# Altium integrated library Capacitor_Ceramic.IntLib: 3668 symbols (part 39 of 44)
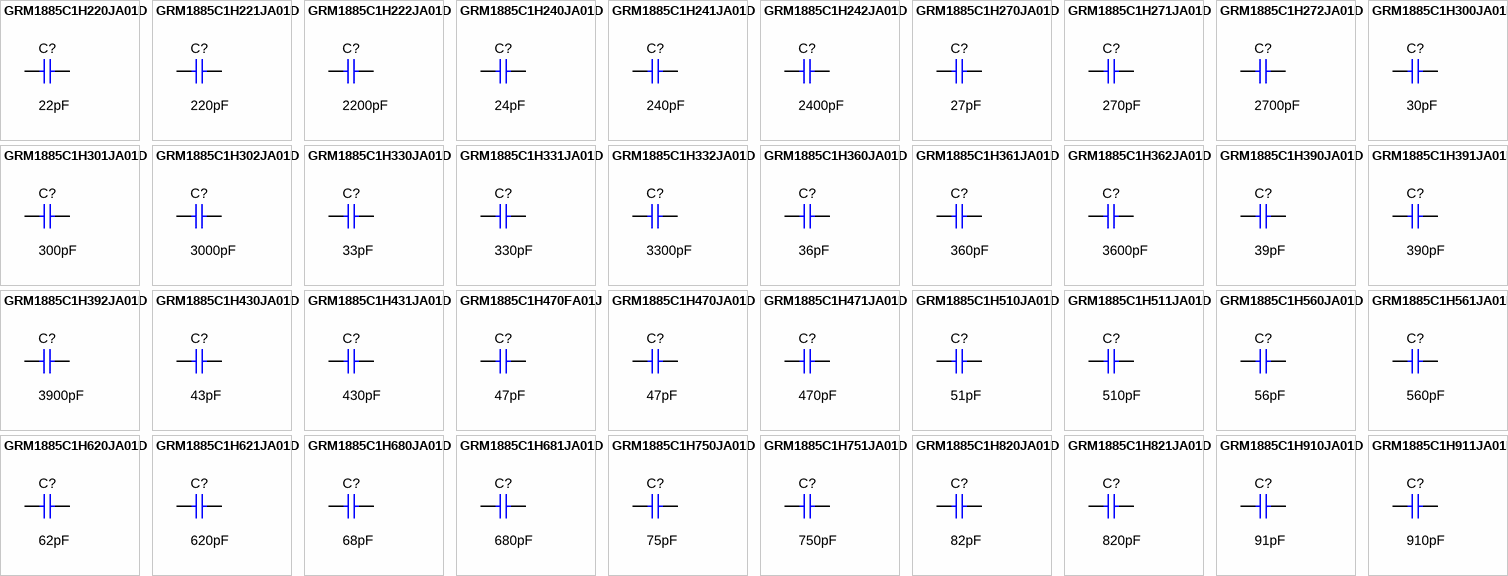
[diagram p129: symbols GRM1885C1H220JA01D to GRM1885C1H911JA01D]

## GRM1885C1H751JA01D
designator C?  ValueDisplayed: 750pF  (hidden comment: GRM1885C1H751JA01D)
CAP, CERM, 750 pF, 50 V,+/- 5%, C0G/NP0, 0603; Manufacturer: MuRata; Polarized: N; CompType: Capacitor; Value: 750pF; U/M: EA; Cap_F: 0.00000000075; Tolerance_%: 5; VDC_V: 50; Value2: 50V; TaMin_C: -55; TaMax_C: 125; Cap_Case: 0603; SizeArea_mm2: 1.28; SizeAreaWB_mm2: 4.68; SizeX_mm: 1.6; SizeY_mm: 0.8; SizeZ_mm: 1; AEC Category: Q200; Green_Lifecycle: Active; Green_REACh: Passed
signal-integrity model Cap
simulation model Cap
footprint 0603
footprint 0603M
footprint 0603L
footprint 0603_HV
footprint 0603S
pins: 1, 2

## GRM1885C1H820JA01D
designator C?  ValueDisplayed: 82pF  (hidden comment: GRM1885C1H820JA01D)
CAP, CERM, 82 pF, 50 V,+/- 5%, C0G/NP0, 0603; Manufacturer: MuRata; Polarized: N; CompType: Capacitor; Value: 82pF; U/M: EA; Cap_F: 0.000000000082; Tolerance_%: 5; VDC_V: 50; Value2: 50V; TaMin_C: -55; TaMax_C: 125; Cap_Case: 0603; SizeArea_mm2: 1.28; SizeAreaWB_mm2: 4.68; SizeX_mm: 1.6; SizeY_mm: 0.8; SizeZ_mm: 1; AEC Category: Q200; Green_Lifecycle: Active; Green_REACh: Passed
signal-integrity model Cap
simulation model Cap
footprint 0603
footprint 0603M
footprint 0603L
footprint 0603_HV
footprint 0603S
pins: 1, 2

## GRM1885C1H821JA01D
designator C?  ValueDisplayed: 820pF  (hidden comment: GRM1885C1H821JA01D)
CAP, CERM, 820 pF, 50 V,+/- 5%, C0G/NP0, 0603; Manufacturer: MuRata; Polarized: N; CompType: Capacitor; Value: 820pF; U/M: EA; Cap_F: 0.00000000082; Tolerance_%: 5; VDC_V: 50; Value2: 50V; TaMin_C: -55; TaMax_C: 125; Cap_Case: 0603; SizeArea_mm2: 1.28; SizeAreaWB_mm2: 4.68; SizeX_mm: 1.6; SizeY_mm: 0.8; SizeZ_mm: 1; AEC Category: Q200; Green_Lifecycle: Active; Green_REACh: Passed
signal-integrity model Cap
simulation model Cap
footprint 0603
footprint 0603M
footprint 0603L
footprint 0603_HV
footprint 0603S
pins: 1, 2

## GRM1885C1H910JA01D
designator C?  ValueDisplayed: 91pF  (hidden comment: GRM1885C1H910JA01D)
CAP, CERM, 91 pF, 50 V,+/- 5%, C0G/NP0, 0603; Manufacturer: MuRata; Polarized: N; CompType: Capacitor; Value: 91pF; U/M: EA; Cap_F: 0.000000000091; Tolerance_%: 5; VDC_V: 50; Value2: 50V; TaMin_C: -55; TaMax_C: 125; Cap_Case: 0603; SizeArea_mm2: 1.28; SizeAreaWB_mm2: 4.68; SizeX_mm: 1.6; SizeY_mm: 0.8; SizeZ_mm: 1; AEC Category: Q200
signal-integrity model Cap
simulation model Cap
footprint 0603
footprint 0603M
footprint 0603L
footprint 0603_HV
footprint 0603S
pins: 1, 2

## GRM1885C1H911JA01D
designator C?  ValueDisplayed: 910pF  (hidden comment: GRM1885C1H911JA01D)
CAP, CERM, 910 pF, 50 V,+/- 5%, C0G/NP0, 0603; Manufacturer: MuRata; Polarized: N; CompType: Capacitor; Value: 910pF; U/M: EA; Cap_F: 0.00000000091; Tolerance_%: 5; VDC_V: 50; Value2: 50V; TaMin_C: -55; TaMax_C: 125; Cap_Case: 0603; SizeArea_mm2: 1.28; SizeAreaWB_mm2: 4.68; SizeX_mm: 1.6; SizeY_mm: 0.8; SizeZ_mm: 1; AEC Category: Q200
signal-integrity model Cap
simulation model Cap
footprint 0603
footprint 0603M
footprint 0603L
footprint 0603_HV
footprint 0603S
pins: 1, 2

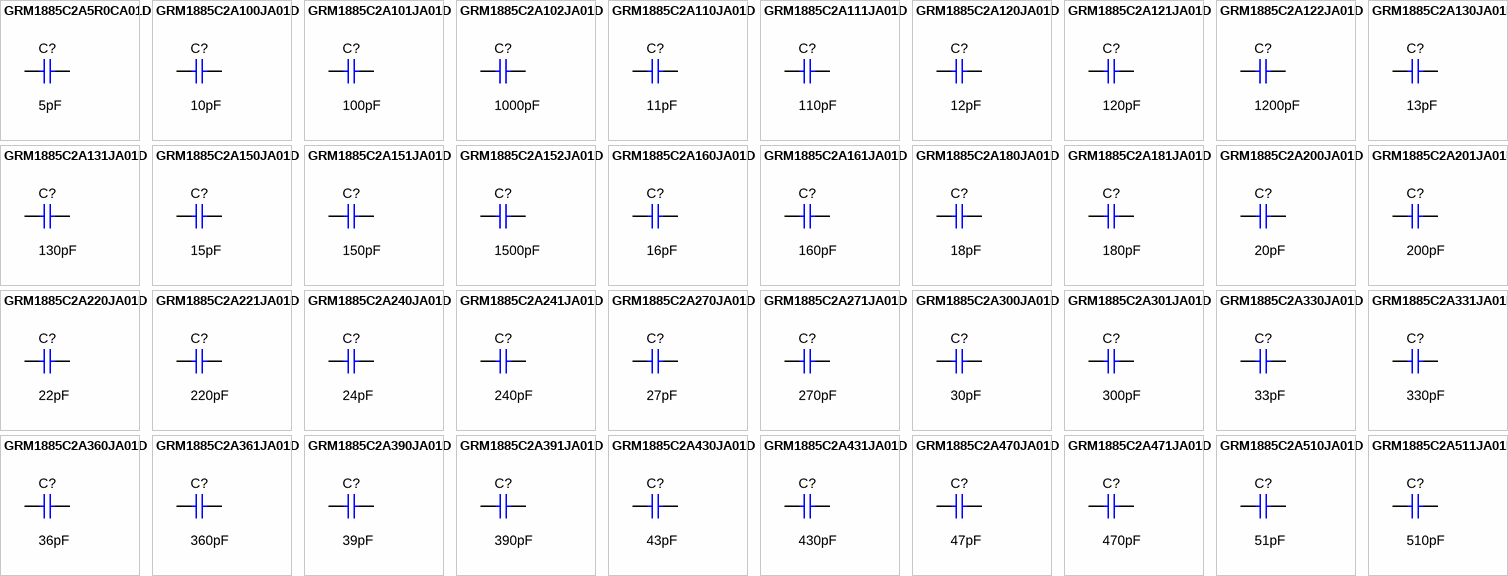
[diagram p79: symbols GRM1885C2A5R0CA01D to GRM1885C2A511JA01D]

## GRM1885C2A5R0CA01D
designator C?  ValueDisplayed: 5pF  (hidden comment: GRM1885C2A5R0CA01D)
CAP, CERM, 5 pF, 100 V,+/- 5%, C0G/NP0, 0603; Manufacturer: MuRata; Polarized: N; CompType: Capacitor; Value: 5pF; U/M: EA; Cap_F: 0.000000000005; Tolerance_%: 5; VDC_V: 100; Value2: 100V; TaMin_C: -55; TaMax_C: 125; Cap_Case: 0603; SizeArea_mm2: 1.28; SizeAreaWB_mm2: 4.68; SizeX_mm: 1.6; SizeY_mm: 0.8; SizeZ_mm: 1; AEC Category: Q200
signal-integrity model Cap
simulation model Cap
footprint 0603
footprint 0603M
footprint 0603L
footprint 0603_HV
footprint 0603S
pins: 1, 2

## GRM1885C2A100JA01D
designator C?  ValueDisplayed: 10pF  (hidden comment: GRM1885C2A100JA01D)
CAP, CERM, 10 pF, 100 V,+/- 5%, C0G/NP0, 0603; Manufacturer: MuRata; Polarized: N; CompType: Capacitor; Value: 10pF; U/M: EA; Cap_F: 0.00000000001; Tolerance_%: 5; VDC_V: 100; Value2: 100V; TaMin_C: -55; TaMax_C: 125; Cap_Case: 0603; SizeArea_mm2: 1.28; SizeAreaWB_mm2: 4.68; SizeX_mm: 1.6; SizeY_mm: 0.8; SizeZ_mm: 1; AEC Category: Q200; Green_Lifecycle: Active; Green_REACh: Passed
signal-integrity model Cap
simulation model Cap
footprint 0603
footprint 0603M
footprint 0603L
footprint 0603_HV
footprint 0603S
pins: 1, 2

## GRM1885C2A101JA01D
designator C?  ValueDisplayed: 100pF  (hidden comment: GRM1885C2A101JA01D)
CAP, CERM, 100 pF, 100 V,+/- 5%, C0G/NP0, 0603; Manufacturer: MuRata; Polarized: N; CompType: Capacitor; Value: 100pF; U/M: EA; Cap_F: 0.0000000001; Tolerance_%: 5; VDC_V: 100; Value2: 100V; TaMin_C: -55; TaMax_C: 125; Cap_Case: 0603; SizeArea_mm2: 1.28; SizeAreaWB_mm2: 4.68; SizeX_mm: 1.6; SizeY_mm: 0.8; SizeZ_mm: 1; AEC Category: Q200; Green_Lifecycle: Active; Green_REACh: Passed
signal-integrity model Cap
simulation model Cap
footprint 0603
footprint 0603M
footprint 0603L
footprint 0603_HV
footprint 0603S
pins: 1, 2

## GRM1885C2A102JA01D
designator C?  ValueDisplayed: 1000pF  (hidden comment: GRM1885C2A102JA01D)
CAP, CERM, 1000 pF, 100 V,+/- 5%, C0G/NP0, 0603; Manufacturer: MuRata; Polarized: N; CompType: Capacitor; Value: 1000pF; U/M: EA; Cap_F: 0.000000001; Tolerance_%: 5; VDC_V: 100; Value2: 100V; TaMin_C: -55; TaMax_C: 125; Cap_Case: 0603; SizeArea_mm2: 1.28; SizeAreaWB_mm2: 4.68; SizeX_mm: 1.6; SizeY_mm: 0.8; SizeZ_mm: 1; AEC Category: Q200; Green_Lifecycle: Active; Green_REACh: Passed
signal-integrity model Cap
simulation model Cap
footprint 0603
footprint 0603M
footprint 0603L
footprint 0603_HV
footprint 0603S
pins: 1, 2

## GRM1885C2A110JA01D
designator C?  ValueDisplayed: 11pF  (hidden comment: GRM1885C2A110JA01D)
CAP, CERM, 11 pF, 100 V,+/- 5%, C0G/NP0, 0603; Manufacturer: MuRata; Polarized: N; CompType: Capacitor; Value: 11pF; U/M: EA; Cap_F: 0.000000000011; Tolerance_%: 5; VDC_V: 100; Value2: 100V; TaMin_C: -55; TaMax_C: 125; Cap_Case: 0603; SizeArea_mm2: 1.28; SizeAreaWB_mm2: 4.68; SizeX_mm: 1.6; SizeY_mm: 0.8; SizeZ_mm: 1; AEC Category: Q200
signal-integrity model Cap
simulation model Cap
footprint 0603
footprint 0603M
footprint 0603L
footprint 0603_HV
footprint 0603S
pins: 1, 2

## GRM1885C2A111JA01D
designator C?  ValueDisplayed: 110pF  (hidden comment: GRM1885C2A111JA01D)
CAP, CERM, 110 pF, 100 V,+/- 5%, C0G/NP0, 0603; Manufacturer: MuRata; Polarized: N; CompType: Capacitor; Value: 110pF; U/M: EA; Cap_F: 0.00000000011; Tolerance_%: 5; VDC_V: 100; Value2: 100V; TaMin_C: -55; TaMax_C: 125; Cap_Case: 0603; SizeArea_mm2: 1.28; SizeAreaWB_mm2: 4.68; SizeX_mm: 1.6; SizeY_mm: 0.8; SizeZ_mm: 1; AEC Category: Q200
signal-integrity model Cap
simulation model Cap
footprint 0603
footprint 0603M
footprint 0603L
footprint 0603_HV
footprint 0603S
pins: 1, 2

## GRM1885C2A120JA01D
designator C?  ValueDisplayed: 12pF  (hidden comment: GRM1885C2A120JA01D)
CAP, CERM, 12 pF, 100 V,+/- 5%, C0G/NP0, 0603; Manufacturer: MuRata; Polarized: N; CompType: Capacitor; Value: 12pF; U/M: EA; Cap_F: 0.000000000012; Tolerance_%: 5; VDC_V: 100; Value2: 100V; TaMin_C: -55; TaMax_C: 125; Cap_Case: 0603; SizeArea_mm2: 1.28; SizeAreaWB_mm2: 4.68; SizeX_mm: 1.6; SizeY_mm: 0.8; SizeZ_mm: 1; AEC Category: Q200
signal-integrity model Cap
simulation model Cap
footprint 0603
footprint 0603M
footprint 0603L
footprint 0603_HV
footprint 0603S
pins: 1, 2

## GRM1885C2A121JA01D
designator C?  ValueDisplayed: 120pF  (hidden comment: GRM1885C2A121JA01D)
CAP, CERM, 120 pF, 100 V,+/- 5%, C0G/NP0, 0603; Manufacturer: MuRata; Polarized: N; CompType: Capacitor; Value: 120pF; U/M: EA; Cap_F: 0.00000000012; Tolerance_%: 5; VDC_V: 100; Value2: 100V; TaMin_C: -55; TaMax_C: 125; Cap_Case: 0603; SizeArea_mm2: 1.28; SizeAreaWB_mm2: 4.68; SizeX_mm: 1.6; SizeY_mm: 0.8; SizeZ_mm: 1; AEC Category: Q200
signal-integrity model Cap
simulation model Cap
footprint 0603
footprint 0603M
footprint 0603L
footprint 0603_HV
footprint 0603S
pins: 1, 2

## GRM1885C2A122JA01D
designator C?  ValueDisplayed: 1200pF  (hidden comment: GRM1885C2A122JA01D)
CAP, CERM, 1200 pF, 100 V,+/- 5%, C0G/NP0, 0603; Manufacturer: MuRata; Polarized: N; CompType: Capacitor; Value: 1200pF; U/M: EA; Cap_F: 0.0000000012; Tolerance_%: 5; VDC_V: 100; Value2: 100V; TaMin_C: -55; TaMax_C: 125; Cap_Case: 0603; SizeArea_mm2: 1.28; SizeAreaWB_mm2: 4.68; SizeX_mm: 1.6; SizeY_mm: 0.8; SizeZ_mm: 1; AEC Category: Q200; Green_Lifecycle: Active; Green_REACh: Passed
signal-integrity model Cap
simulation model Cap
footprint 0603
footprint 0603M
footprint 0603L
footprint 0603_HV
footprint 0603S
pins: 1, 2

## GRM1885C2A130JA01D
designator C?  ValueDisplayed: 13pF  (hidden comment: GRM1885C2A130JA01D)
CAP, CERM, 13 pF, 100 V,+/- 5%, C0G/NP0, 0603; Manufacturer: MuRata; Polarized: N; CompType: Capacitor; Value: 13pF; U/M: EA; Cap_F: 0.000000000013; Tolerance_%: 5; VDC_V: 100; Value2: 100V; TaMin_C: -55; TaMax_C: 125; Cap_Case: 0603; SizeArea_mm2: 1.28; SizeAreaWB_mm2: 4.68; SizeX_mm: 1.6; SizeY_mm: 0.8; SizeZ_mm: 1; AEC Category: Q200
signal-integrity model Cap
simulation model Cap
footprint 0603
footprint 0603M
footprint 0603L
footprint 0603_HV
footprint 0603S
pins: 1, 2

## GRM1885C2A131JA01D
designator C?  ValueDisplayed: 130pF  (hidden comment: GRM1885C2A131JA01D)
CAP, CERM, 130 pF, 100 V,+/- 5%, C0G/NP0, 0603; Manufacturer: MuRata; Polarized: N; CompType: Capacitor; Value: 130pF; U/M: EA; Cap_F: 0.00000000013; Tolerance_%: 5; VDC_V: 100; Value2: 100V; TaMin_C: -55; TaMax_C: 125; Cap_Case: 0603; SizeArea_mm2: 1.28; SizeAreaWB_mm2: 4.68; SizeX_mm: 1.6; SizeY_mm: 0.8; SizeZ_mm: 1; AEC Category: Q200
signal-integrity model Cap
simulation model Cap
footprint 0603
footprint 0603M
footprint 0603L
footprint 0603_HV
footprint 0603S
pins: 1, 2

## GRM1885C2A150JA01D
designator C?  ValueDisplayed: 15pF  (hidden comment: GRM1885C2A150JA01D)
CAP, CERM, 15 pF, 100 V,+/- 5%, C0G/NP0, 0603; Manufacturer: MuRata; Polarized: N; CompType: Capacitor; Value: 15pF; U/M: EA; Cap_F: 0.000000000015; Tolerance_%: 5; VDC_V: 100; Value2: 100V; TaMin_C: -55; TaMax_C: 125; Cap_Case: 0603; SizeArea_mm2: 1.28; SizeAreaWB_mm2: 4.68; SizeX_mm: 1.6; SizeY_mm: 0.8; SizeZ_mm: 1; AEC Category: Q200; Green_Lifecycle: Active; Green_REACh: Passed
signal-integrity model Cap
simulation model Cap
footprint 0603
footprint 0603M
footprint 0603L
footprint 0603_HV
footprint 0603S
pins: 1, 2

## GRM1885C2A151JA01D
designator C?  ValueDisplayed: 150pF  (hidden comment: GRM1885C2A151JA01D)
CAP, CERM, 150 pF, 100 V,+/- 5%, C0G/NP0, 0603; Manufacturer: MuRata; Polarized: N; CompType: Capacitor; Value: 150pF; U/M: EA; Cap_F: 0.00000000015; Tolerance_%: 5; VDC_V: 100; Value2: 100V; TaMin_C: -55; TaMax_C: 125; Cap_Case: 0603; SizeArea_mm2: 1.28; SizeAreaWB_mm2: 4.68; SizeX_mm: 1.6; SizeY_mm: 0.8; SizeZ_mm: 1; AEC Category: Q200
signal-integrity model Cap
simulation model Cap
footprint 0603
footprint 0603M
footprint 0603L
footprint 0603_HV
footprint 0603S
pins: 1, 2

## GRM1885C2A152JA01D
designator C?  ValueDisplayed: 1500pF  (hidden comment: GRM1885C2A152JA01D)
CAP, CERM, 1500 pF, 100 V,+/- 5%, C0G/NP0, 0603; Manufacturer: MuRata; Polarized: N; CompType: Capacitor; Value: 1500pF; U/M: EA; Cap_F: 0.0000000015; Tolerance_%: 5; VDC_V: 100; Value2: 100V; TaMin_C: -55; TaMax_C: 125; Cap_Case: 0603; SizeArea_mm2: 1.28; SizeAreaWB_mm2: 4.68; SizeX_mm: 1.6; SizeY_mm: 0.8; SizeZ_mm: 1; AEC Category: Q200; Green_Lifecycle: Active; Green_REACh: Passed
signal-integrity model Cap
simulation model Cap
footprint 0603
footprint 0603M
footprint 0603L
footprint 0603_HV
footprint 0603S
pins: 1, 2

## GRM1885C2A160JA01D
designator C?  ValueDisplayed: 16pF  (hidden comment: GRM1885C2A160JA01D)
CAP, CERM, 16 pF, 100 V,+/- 5%, C0G/NP0, 0603; Manufacturer: MuRata; Polarized: N; CompType: Capacitor; Value: 16pF; U/M: EA; Cap_F: 0.000000000016; Tolerance_%: 5; VDC_V: 100; Value2: 100V; TaMin_C: -55; TaMax_C: 125; Cap_Case: 0603; SizeArea_mm2: 1.28; SizeAreaWB_mm2: 4.68; SizeX_mm: 1.6; SizeY_mm: 0.8; SizeZ_mm: 1; AEC Category: Q200
signal-integrity model Cap
simulation model Cap
footprint 0603
footprint 0603M
footprint 0603L
footprint 0603_HV
footprint 0603S
pins: 1, 2

## GRM1885C2A161JA01D
designator C?  ValueDisplayed: 160pF  (hidden comment: GRM1885C2A161JA01D)
CAP, CERM, 160 pF, 100 V,+/- 5%, C0G/NP0, 0603; Manufacturer: MuRata; Polarized: N; CompType: Capacitor; Value: 160pF; U/M: EA; Cap_F: 0.00000000016; Tolerance_%: 5; VDC_V: 100; Value2: 100V; TaMin_C: -55; TaMax_C: 125; Cap_Case: 0603; SizeArea_mm2: 1.28; SizeAreaWB_mm2: 4.68; SizeX_mm: 1.6; SizeY_mm: 0.8; SizeZ_mm: 1; AEC Category: Q200
signal-integrity model Cap
simulation model Cap
footprint 0603
footprint 0603M
footprint 0603L
footprint 0603_HV
footprint 0603S
pins: 1, 2

## GRM1885C2A180JA01D
designator C?  ValueDisplayed: 18pF  (hidden comment: GRM1885C2A180JA01D)
CAP, CERM, 18 pF, 100 V,+/- 5%, C0G/NP0, 0603; Manufacturer: MuRata; Polarized: N; CompType: Capacitor; Value: 18pF; U/M: EA; Cap_F: 0.000000000018; Tolerance_%: 5; VDC_V: 100; Value2: 100V; TaMin_C: -55; TaMax_C: 125; Cap_Case: 0603; SizeArea_mm2: 1.28; SizeAreaWB_mm2: 4.68; SizeX_mm: 1.6; SizeY_mm: 0.8; SizeZ_mm: 1; AEC Category: Q200; Green_Lifecycle: Active; Green_REACh: Passed
signal-integrity model Cap
simulation model Cap
footprint 0603
footprint 0603M
footprint 0603L
footprint 0603_HV
footprint 0603S
pins: 1, 2

## GRM1885C2A181JA01D
designator C?  ValueDisplayed: 180pF  (hidden comment: GRM1885C2A181JA01D)
CAP, CERM, 180 pF, 100 V,+/- 5%, C0G/NP0, 0603; Manufacturer: MuRata; Polarized: N; CompType: Capacitor; Value: 180pF; U/M: EA; Cap_F: 0.00000000018; Tolerance_%: 5; VDC_V: 100; Value2: 100V; TaMin_C: -55; TaMax_C: 125; Cap_Case: 0603; SizeArea_mm2: 1.28; SizeAreaWB_mm2: 4.68; SizeX_mm: 1.6; SizeY_mm: 0.8; SizeZ_mm: 1; AEC Category: Q200
signal-integrity model Cap
simulation model Cap
footprint 0603
footprint 0603M
footprint 0603L
footprint 0603_HV
footprint 0603S
pins: 1, 2

## GRM1885C2A200JA01D
designator C?  ValueDisplayed: 20pF  (hidden comment: GRM1885C2A200JA01D)
CAP, CERM, 20 pF, 100 V,+/- 5%, C0G/NP0, 0603; Manufacturer: MuRata; Polarized: N; CompType: Capacitor; Value: 20pF; U/M: EA; Cap_F: 0.00000000002; Tolerance_%: 5; VDC_V: 100; Value2: 100V; TaMin_C: -55; TaMax_C: 125; Cap_Case: 0603; SizeArea_mm2: 1.28; SizeAreaWB_mm2: 4.68; SizeX_mm: 1.6; SizeY_mm: 0.8; SizeZ_mm: 1; AEC Category: Q200; Green_Lifecycle: Active; Green_REACh: Passed
signal-integrity model Cap
simulation model Cap
footprint 0603
footprint 0603M
footprint 0603L
footprint 0603_HV
footprint 0603S
pins: 1, 2

## GRM1885C2A201JA01D
designator C?  ValueDisplayed: 200pF  (hidden comment: GRM1885C2A201JA01D)
CAP, CERM, 200 pF, 100 V,+/- 5%, C0G/NP0, 0603; Manufacturer: MuRata; Polarized: N; CompType: Capacitor; Value: 200pF; U/M: EA; Cap_F: 0.0000000002; Tolerance_%: 5; VDC_V: 100; Value2: 100V; TaMin_C: -55; TaMax_C: 125; Cap_Case: 0603; SizeArea_mm2: 1.28; SizeAreaWB_mm2: 4.68; SizeX_mm: 1.6; SizeY_mm: 0.8; SizeZ_mm: 1; AEC Category: Q200
signal-integrity model Cap
simulation model Cap
footprint 0603
footprint 0603M
footprint 0603L
footprint 0603_HV
footprint 0603S
pins: 1, 2

## GRM1885C2A220JA01D
designator C?  ValueDisplayed: 22pF  (hidden comment: GRM1885C2A220JA01D)
CAP, CERM, 22 pF, 100 V,+/- 5%, C0G/NP0, 0603; Manufacturer: MuRata; Polarized: N; CompType: Capacitor; Value: 22pF; U/M: EA; Cap_F: 0.000000000022; Tolerance_%: 5; VDC_V: 100; Value2: 100V; TaMin_C: -55; TaMax_C: 125; Cap_Case: 0603; SizeArea_mm2: 1.28; SizeAreaWB_mm2: 4.68; SizeX_mm: 1.6; SizeY_mm: 0.8; SizeZ_mm: 1; AEC Category: Q200
signal-integrity model Cap
simulation model Cap
footprint 0603
footprint 0603M
footprint 0603L
footprint 0603_HV
footprint 0603S
pins: 1, 2

## GRM1885C2A221JA01D
designator C?  ValueDisplayed: 220pF  (hidden comment: GRM1885C2A221JA01D)
CAP, CERM, 220 pF, 100 V,+/- 5%, C0G/NP0, 0603; Manufacturer: MuRata; Polarized: N; CompType: Capacitor; Value: 220pF; U/M: EA; Cap_F: 0.00000000022; Tolerance_%: 5; VDC_V: 100; Value2: 100V; TaMin_C: -55; TaMax_C: 125; Cap_Case: 0603; SizeArea_mm2: 1.28; SizeAreaWB_mm2: 4.68; SizeX_mm: 1.6; SizeY_mm: 0.8; SizeZ_mm: 1; AEC Category: Q200
signal-integrity model Cap
simulation model Cap
footprint 0603
footprint 0603M
footprint 0603L
footprint 0603_HV
footprint 0603S
pins: 1, 2

## GRM1885C2A240JA01D
designator C?  ValueDisplayed: 24pF  (hidden comment: GRM1885C2A240JA01D)
CAP, CERM, 24 pF, 100 V,+/- 5%, C0G/NP0, 0603; Manufacturer: MuRata; Polarized: N; CompType: Capacitor; Value: 24pF; U/M: EA; Cap_F: 0.000000000024; Tolerance_%: 5; VDC_V: 100; Value2: 100V; TaMin_C: -55; TaMax_C: 125; Cap_Case: 0603; SizeArea_mm2: 1.28; SizeAreaWB_mm2: 4.68; SizeX_mm: 1.6; SizeY_mm: 0.8; SizeZ_mm: 1; AEC Category: Q200
signal-integrity model Cap
simulation model Cap
footprint 0603
footprint 0603M
footprint 0603L
footprint 0603_HV
footprint 0603S
pins: 1, 2

## GRM1885C2A241JA01D
designator C?  ValueDisplayed: 240pF  (hidden comment: GRM1885C2A241JA01D)
CAP, CERM, 240 pF, 100 V,+/- 5%, C0G/NP0, 0603; Manufacturer: MuRata; Polarized: N; CompType: Capacitor; Value: 240pF; U/M: EA; Cap_F: 0.00000000024; Tolerance_%: 5; VDC_V: 100; Value2: 100V; TaMin_C: -55; TaMax_C: 125; Cap_Case: 0603; SizeArea_mm2: 1.28; SizeAreaWB_mm2: 4.68; SizeX_mm: 1.6; SizeY_mm: 0.8; SizeZ_mm: 1; AEC Category: Q200
signal-integrity model Cap
simulation model Cap
footprint 0603
footprint 0603M
footprint 0603L
footprint 0603_HV
footprint 0603S
pins: 1, 2

## GRM1885C2A270JA01D
designator C?  ValueDisplayed: 27pF  (hidden comment: GRM1885C2A270JA01D)
CAP, CERM, 27 pF, 100 V,+/- 5%, C0G/NP0, 0603; Manufacturer: MuRata; Polarized: N; CompType: Capacitor; Value: 27pF; U/M: EA; Cap_F: 0.000000000027; Tolerance_%: 5; VDC_V: 100; Value2: 100V; TaMin_C: -55; TaMax_C: 125; Cap_Case: 0603; SizeArea_mm2: 1.28; SizeAreaWB_mm2: 4.68; SizeX_mm: 1.6; SizeY_mm: 0.8; SizeZ_mm: 1; AEC Category: Q200
signal-integrity model Cap
simulation model Cap
footprint 0603
footprint 0603M
footprint 0603L
footprint 0603_HV
footprint 0603S
pins: 1, 2

## GRM1885C2A271JA01D
designator C?  ValueDisplayed: 270pF  (hidden comment: GRM1885C2A271JA01D)
CAP, CERM, 270 pF, 100 V,+/- 5%, C0G/NP0, 0603; Manufacturer: MuRata; Polarized: N; CompType: Capacitor; Value: 270pF; U/M: EA; Cap_F: 0.00000000027; Tolerance_%: 5; VDC_V: 100; Value2: 100V; TaMin_C: -55; TaMax_C: 125; Cap_Case: 0603; SizeArea_mm2: 1.28; SizeAreaWB_mm2: 4.68; SizeX_mm: 1.6; SizeY_mm: 0.8; SizeZ_mm: 1; AEC Category: Q200; Green_Lifecycle: Active; Green_REACh: Passed
signal-integrity model Cap
simulation model Cap
footprint 0603
footprint 0603M
footprint 0603L
footprint 0603_HV
footprint 0603S
pins: 1, 2

## GRM1885C2A300JA01D
designator C?  ValueDisplayed: 30pF  (hidden comment: GRM1885C2A300JA01D)
CAP, CERM, 30 pF, 100 V,+/- 5%, C0G/NP0, 0603; Manufacturer: MuRata; Polarized: N; CompType: Capacitor; Value: 30pF; U/M: EA; Cap_F: 0.00000000003; Tolerance_%: 5; VDC_V: 100; Value2: 100V; TaMin_C: -55; TaMax_C: 125; Cap_Case: 0603; SizeArea_mm2: 1.28; SizeAreaWB_mm2: 4.68; SizeX_mm: 1.6; SizeY_mm: 0.8; SizeZ_mm: 1; AEC Category: Q200; Green_Lifecycle: Active; Green_REACh: Passed
signal-integrity model Cap
simulation model Cap
footprint 0603
footprint 0603M
footprint 0603L
footprint 0603_HV
footprint 0603S
pins: 1, 2

## GRM1885C2A301JA01D
designator C?  ValueDisplayed: 300pF  (hidden comment: GRM1885C2A301JA01D)
CAP, CERM, 300 pF, 100 V,+/- 5%, C0G/NP0, 0603; Manufacturer: MuRata; Polarized: N; CompType: Capacitor; Value: 300pF; U/M: EA; Cap_F: 0.0000000003; Tolerance_%: 5; VDC_V: 100; Value2: 100V; TaMin_C: -55; TaMax_C: 125; Cap_Case: 0603; SizeArea_mm2: 1.28; SizeAreaWB_mm2: 4.68; SizeX_mm: 1.6; SizeY_mm: 0.8; SizeZ_mm: 1; AEC Category: Q200
signal-integrity model Cap
simulation model Cap
footprint 0603
footprint 0603M
footprint 0603L
footprint 0603_HV
footprint 0603S
pins: 1, 2

## GRM1885C2A330JA01D
designator C?  ValueDisplayed: 33pF  (hidden comment: GRM1885C2A330JA01D)
CAP, CERM, 33 pF, 100 V,+/- 5%, C0G/NP0, 0603; Manufacturer: MuRata; Polarized: N; CompType: Capacitor; Value: 33pF; U/M: EA; Cap_F: 0.000000000033; Tolerance_%: 5; VDC_V: 100; Value2: 100V; TaMin_C: -55; TaMax_C: 125; Cap_Case: 0603; SizeArea_mm2: 1.28; SizeAreaWB_mm2: 4.68; SizeX_mm: 1.6; SizeY_mm: 0.8; SizeZ_mm: 1; AEC Category: Q200; Green_Lifecycle: Active; Green_REACh: Passed
signal-integrity model Cap
simulation model Cap
footprint 0603
footprint 0603M
footprint 0603L
footprint 0603_HV
footprint 0603S
pins: 1, 2

## GRM1885C2A331JA01D
designator C?  ValueDisplayed: 330pF  (hidden comment: GRM1885C2A331JA01D)
CAP, CERM, 330 pF, 100 V,+/- 5%, C0G/NP0, 0603; Manufacturer: MuRata; Polarized: N; CompType: Capacitor; Value: 330pF; U/M: EA; Cap_F: 0.00000000033; Tolerance_%: 5; VDC_V: 100; Value2: 100V; TaMin_C: -55; TaMax_C: 125; Cap_Case: 0603; SizeArea_mm2: 1.28; SizeAreaWB_mm2: 4.68; SizeX_mm: 1.6; SizeY_mm: 0.8; SizeZ_mm: 1; AEC Category: Q200; Green_Lifecycle: Active; Green_REACh: Passed
signal-integrity model Cap
simulation model Cap
footprint 0603
footprint 0603M
footprint 0603L
footprint 0603_HV
footprint 0603S
pins: 1, 2

## GRM1885C2A360JA01D
designator C?  ValueDisplayed: 36pF  (hidden comment: GRM1885C2A360JA01D)
CAP, CERM, 36 pF, 100 V,+/- 5%, C0G/NP0, 0603; Manufacturer: MuRata; Polarized: N; CompType: Capacitor; Value: 36pF; U/M: EA; Cap_F: 0.000000000036; Tolerance_%: 5; VDC_V: 100; Value2: 100V; TaMin_C: -55; TaMax_C: 125; Cap_Case: 0603; SizeArea_mm2: 1.28; SizeAreaWB_mm2: 4.68; SizeX_mm: 1.6; SizeY_mm: 0.8; SizeZ_mm: 1; AEC Category: Q200; Green_Lifecycle: Active; Green_REACh: Passed
signal-integrity model Cap
simulation model Cap
footprint 0603
footprint 0603M
footprint 0603L
footprint 0603_HV
footprint 0603S
pins: 1, 2

## GRM1885C2A361JA01D
designator C?  ValueDisplayed: 360pF  (hidden comment: GRM1885C2A361JA01D)
CAP, CERM, 360 pF, 100 V,+/- 5%, C0G/NP0, 0603; Manufacturer: MuRata; Polarized: N; CompType: Capacitor; Value: 360pF; U/M: EA; Cap_F: 0.00000000036; Tolerance_%: 5; VDC_V: 100; Value2: 100V; TaMin_C: -55; TaMax_C: 125; Cap_Case: 0603; SizeArea_mm2: 1.28; SizeAreaWB_mm2: 4.68; SizeX_mm: 1.6; SizeY_mm: 0.8; SizeZ_mm: 1; AEC Category: Q200
signal-integrity model Cap
simulation model Cap
footprint 0603
footprint 0603M
footprint 0603L
footprint 0603_HV
footprint 0603S
pins: 1, 2

## GRM1885C2A390JA01D
designator C?  ValueDisplayed: 39pF  (hidden comment: GRM1885C2A390JA01D)
CAP, CERM, 39 pF, 100 V,+/- 5%, C0G/NP0, 0603; Manufacturer: MuRata; Polarized: N; CompType: Capacitor; Value: 39pF; U/M: EA; Cap_F: 0.000000000039; Tolerance_%: 5; VDC_V: 100; Value2: 100V; TaMin_C: -55; TaMax_C: 125; Cap_Case: 0603; SizeArea_mm2: 1.28; SizeAreaWB_mm2: 4.68; SizeX_mm: 1.6; SizeY_mm: 0.8; SizeZ_mm: 1; AEC Category: Q200; Green_Lifecycle: Active; Green_REACh: Passed
signal-integrity model Cap
simulation model Cap
footprint 0603
footprint 0603M
footprint 0603L
footprint 0603_HV
footprint 0603S
pins: 1, 2

## GRM1885C2A391JA01D
designator C?  ValueDisplayed: 390pF  (hidden comment: GRM1885C2A391JA01D)
CAP, CERM, 390 pF, 100 V,+/- 5%, C0G/NP0, 0603; Manufacturer: MuRata; Polarized: N; CompType: Capacitor; Value: 390pF; U/M: EA; Cap_F: 0.00000000039; Tolerance_%: 5; VDC_V: 100; Value2: 100V; TaMin_C: -55; TaMax_C: 125; Cap_Case: 0603; SizeArea_mm2: 1.28; SizeAreaWB_mm2: 4.68; SizeX_mm: 1.6; SizeY_mm: 0.8; SizeZ_mm: 1; AEC Category: Q200
signal-integrity model Cap
simulation model Cap
footprint 0603
footprint 0603M
footprint 0603L
footprint 0603_HV
footprint 0603S
pins: 1, 2

## GRM1885C2A430JA01D
designator C?  ValueDisplayed: 43pF  (hidden comment: GRM1885C2A430JA01D)
CAP, CERM, 43 pF, 100 V,+/- 5%, C0G/NP0, 0603; Manufacturer: MuRata; Polarized: N; CompType: Capacitor; Value: 43pF; U/M: EA; Cap_F: 0.000000000043; Tolerance_%: 5; VDC_V: 100; Value2: 100V; TaMin_C: -55; TaMax_C: 125; Cap_Case: 0603; SizeArea_mm2: 1.28; SizeAreaWB_mm2: 4.68; SizeX_mm: 1.6; SizeY_mm: 0.8; SizeZ_mm: 1; AEC Category: Q200
signal-integrity model Cap
simulation model Cap
footprint 0603
footprint 0603M
footprint 0603L
footprint 0603_HV
footprint 0603S
pins: 1, 2

## GRM1885C2A431JA01D
designator C?  ValueDisplayed: 430pF  (hidden comment: GRM1885C2A431JA01D)
CAP, CERM, 430 pF, 100 V,+/- 5%, C0G/NP0, 0603; Manufacturer: MuRata; Polarized: N; CompType: Capacitor; Value: 430pF; U/M: EA; Cap_F: 0.00000000043; Tolerance_%: 5; VDC_V: 100; Value2: 100V; TaMin_C: -55; TaMax_C: 125; Cap_Case: 0603; SizeArea_mm2: 1.28; SizeAreaWB_mm2: 4.68; SizeX_mm: 1.6; SizeY_mm: 0.8; SizeZ_mm: 1; AEC Category: Q200
signal-integrity model Cap
simulation model Cap
footprint 0603
footprint 0603M
footprint 0603L
footprint 0603_HV
footprint 0603S
pins: 1, 2

## GRM1885C2A470JA01D
designator C?  ValueDisplayed: 47pF  (hidden comment: GRM1885C2A470JA01D)
CAP, CERM, 47 pF, 100 V,+/- 5%, C0G/NP0, 0603; Manufacturer: MuRata; Polarized: N; CompType: Capacitor; Value: 47pF; U/M: EA; Cap_F: 0.000000000047; Tolerance_%: 5; VDC_V: 100; Value2: 100V; TaMin_C: -55; TaMax_C: 125; Cap_Case: 0603; SizeArea_mm2: 1.28; SizeAreaWB_mm2: 4.68; SizeX_mm: 1.6; SizeY_mm: 0.8; SizeZ_mm: 1; AEC Category: Q200; Green_Lifecycle: Active; Green_REACh: Passed
signal-integrity model Cap
simulation model Cap
footprint 0603
footprint 0603M
footprint 0603L
footprint 0603_HV
footprint 0603S
pins: 1, 2

## GRM1885C2A471JA01D
designator C?  ValueDisplayed: 470pF  (hidden comment: GRM1885C2A471JA01D)
CAP, CERM, 470 pF, 100 V,+/- 5%, C0G/NP0, 0603; Manufacturer: MuRata; Polarized: N; CompType: Capacitor; Value: 470pF; U/M: EA; Cap_F: 0.00000000047; Tolerance_%: 5; VDC_V: 100; Value2: 100V; TaMin_C: -55; TaMax_C: 125; Cap_Case: 0603; SizeArea_mm2: 1.28; SizeAreaWB_mm2: 4.68; SizeX_mm: 1.6; SizeY_mm: 0.8; SizeZ_mm: 1; AEC Category: Q200
signal-integrity model Cap
simulation model Cap
footprint 0603
footprint 0603M
footprint 0603L
footprint 0603_HV
footprint 0603S
pins: 1, 2

## GRM1885C2A510JA01D
designator C?  ValueDisplayed: 51pF  (hidden comment: GRM1885C2A510JA01D)
CAP, CERM, 51 pF, 100 V,+/- 5%, C0G/NP0, 0603; Manufacturer: MuRata; Polarized: N; CompType: Capacitor; Value: 51pF; U/M: EA; Cap_F: 0.000000000051; Tolerance_%: 5; VDC_V: 100; Value2: 100V; TaMin_C: -55; TaMax_C: 125; Cap_Case: 0603; SizeArea_mm2: 1.28; SizeAreaWB_mm2: 4.68; SizeX_mm: 1.6; SizeY_mm: 0.8; SizeZ_mm: 1; AEC Category: Q200; Green_Lifecycle: Active; Green_REACh: Passed
signal-integrity model Cap
simulation model Cap
footprint 0603
footprint 0603M
footprint 0603L
footprint 0603_HV
footprint 0603S
pins: 1, 2

## GRM1885C2A511JA01D
designator C?  ValueDisplayed: 510pF  (hidden comment: GRM1885C2A511JA01D)
CAP, CERM, 510 pF, 100 V,+/- 5%, C0G/NP0, 0603; Manufacturer: MuRata; Polarized: N; CompType: Capacitor; Value: 510pF; U/M: EA; Cap_F: 0.00000000051; Tolerance_%: 5; VDC_V: 100; Value2: 100V; TaMin_C: -55; TaMax_C: 125; Cap_Case: 0603; SizeArea_mm2: 1.28; SizeAreaWB_mm2: 4.68; SizeX_mm: 1.6; SizeY_mm: 0.8; SizeZ_mm: 1; AEC Category: Q200
signal-integrity model Cap
simulation model Cap
footprint 0603
footprint 0603M
footprint 0603L
footprint 0603_HV
footprint 0603S
pins: 1, 2

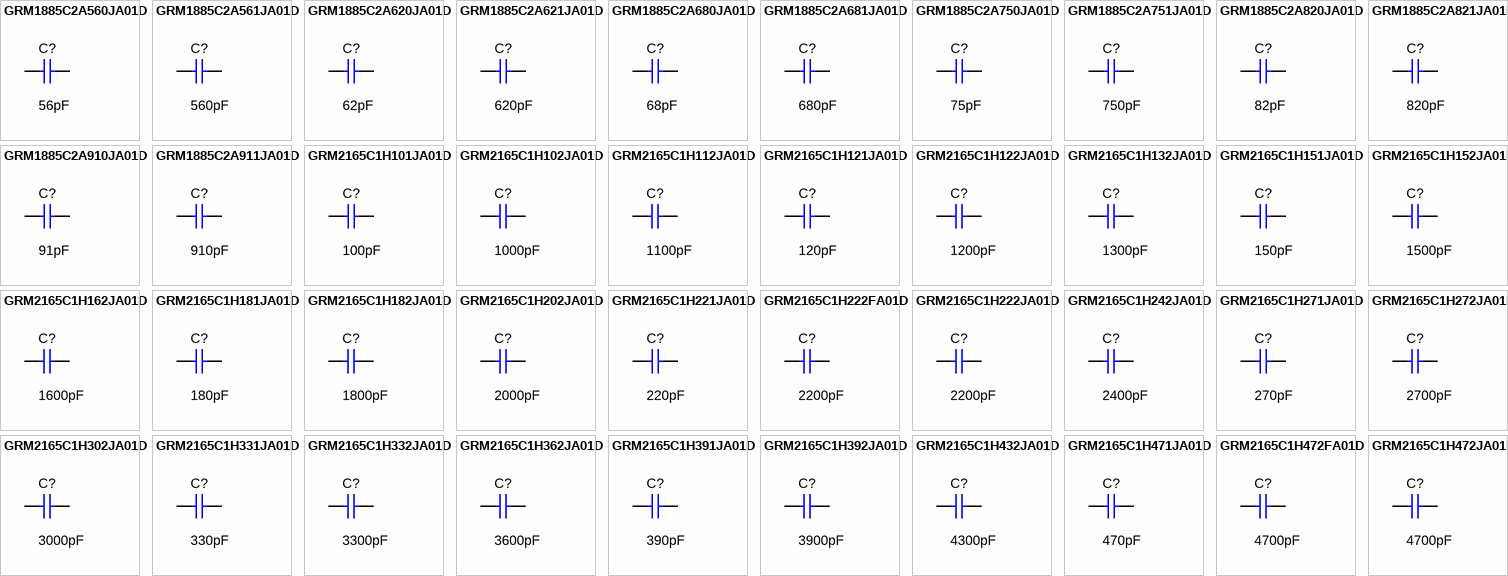
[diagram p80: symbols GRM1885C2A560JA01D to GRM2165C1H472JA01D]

## GRM1885C2A560JA01D
designator C?  ValueDisplayed: 56pF  (hidden comment: GRM1885C2A560JA01D)
CAP, CERM, 56 pF, 100 V,+/- 5%, C0G/NP0, 0603; Manufacturer: MuRata; Polarized: N; CompType: Capacitor; Value: 56pF; U/M: EA; Cap_F: 0.000000000056; Tolerance_%: 5; VDC_V: 100; Value2: 100V; TaMin_C: -55; TaMax_C: 125; Cap_Case: 0603; SizeArea_mm2: 1.28; SizeAreaWB_mm2: 4.68; SizeX_mm: 1.6; SizeY_mm: 0.8; SizeZ_mm: 1; AEC Category: Q200
signal-integrity model Cap
simulation model Cap
footprint 0603
footprint 0603M
footprint 0603L
footprint 0603_HV
footprint 0603S
pins: 1, 2

## GRM1885C2A561JA01D
designator C?  ValueDisplayed: 560pF  (hidden comment: GRM1885C2A561JA01D)
CAP, CERM, 560 pF, 100 V,+/- 5%, C0G/NP0, 0603; Manufacturer: MuRata; Polarized: N; CompType: Capacitor; Value: 560pF; U/M: EA; Cap_F: 0.00000000056; Tolerance_%: 5; VDC_V: 100; Value2: 100V; TaMin_C: -55; TaMax_C: 125; Cap_Case: 0603; SizeArea_mm2: 1.28; SizeAreaWB_mm2: 4.68; SizeX_mm: 1.6; SizeY_mm: 0.8; SizeZ_mm: 1; AEC Category: Q200
signal-integrity model Cap
simulation model Cap
footprint 0603
footprint 0603M
footprint 0603L
footprint 0603_HV
footprint 0603S
pins: 1, 2

## GRM1885C2A620JA01D
designator C?  ValueDisplayed: 62pF  (hidden comment: GRM1885C2A620JA01D)
CAP, CERM, 62 pF, 100 V,+/- 5%, C0G/NP0, 0603; Manufacturer: MuRata; Polarized: N; CompType: Capacitor; Value: 62pF; U/M: EA; Cap_F: 0.000000000062; Tolerance_%: 5; VDC_V: 100; Value2: 100V; TaMin_C: -55; TaMax_C: 125; Cap_Case: 0603; SizeArea_mm2: 1.28; SizeAreaWB_mm2: 4.68; SizeX_mm: 1.6; SizeY_mm: 0.8; SizeZ_mm: 1; AEC Category: Q200
signal-integrity model Cap
simulation model Cap
footprint 0603
footprint 0603M
footprint 0603L
footprint 0603_HV
footprint 0603S
pins: 1, 2

## GRM1885C2A621JA01D
designator C?  ValueDisplayed: 620pF  (hidden comment: GRM1885C2A621JA01D)
CAP, CERM, 620 pF, 100 V,+/- 5%, C0G/NP0, 0603; Manufacturer: MuRata; Polarized: N; CompType: Capacitor; Value: 620pF; U/M: EA; Cap_F: 0.00000000062; Tolerance_%: 5; VDC_V: 100; Value2: 100V; TaMin_C: -55; TaMax_C: 125; Cap_Case: 0603; SizeArea_mm2: 1.28; SizeAreaWB_mm2: 4.68; SizeX_mm: 1.6; SizeY_mm: 0.8; SizeZ_mm: 1; AEC Category: Q200
signal-integrity model Cap
simulation model Cap
footprint 0603
footprint 0603M
footprint 0603L
footprint 0603_HV
footprint 0603S
pins: 1, 2

## GRM1885C2A680JA01D
designator C?  ValueDisplayed: 68pF  (hidden comment: GRM1885C2A680JA01D)
CAP, CERM, 68 pF, 100 V,+/- 5%, C0G/NP0, 0603; Manufacturer: MuRata; Polarized: N; CompType: Capacitor; Value: 68pF; U/M: EA; Cap_F: 0.000000000068; Tolerance_%: 5; VDC_V: 100; Value2: 100V; TaMin_C: -55; TaMax_C: 125; Cap_Case: 0603; SizeArea_mm2: 1.28; SizeAreaWB_mm2: 4.68; SizeX_mm: 1.6; SizeY_mm: 0.8; SizeZ_mm: 1; AEC Category: Q200
signal-integrity model Cap
simulation model Cap
footprint 0603
footprint 0603M
footprint 0603L
footprint 0603_HV
footprint 0603S
pins: 1, 2

## GRM1885C2A681JA01D
designator C?  ValueDisplayed: 680pF  (hidden comment: GRM1885C2A681JA01D)
CAP, CERM, 680 pF, 100 V,+/- 5%, C0G/NP0, 0603; Manufacturer: MuRata; Polarized: N; CompType: Capacitor; Value: 680pF; U/M: EA; Cap_F: 0.00000000068; Tolerance_%: 5; VDC_V: 100; Value2: 100V; TaMin_C: -55; TaMax_C: 125; Cap_Case: 0603; SizeArea_mm2: 1.28; SizeAreaWB_mm2: 4.68; SizeX_mm: 1.6; SizeY_mm: 0.8; SizeZ_mm: 1; AEC Category: Q200
signal-integrity model Cap
simulation model Cap
footprint 0603
footprint 0603M
footprint 0603L
footprint 0603_HV
footprint 0603S
pins: 1, 2

## GRM1885C2A750JA01D
designator C?  ValueDisplayed: 75pF  (hidden comment: GRM1885C2A750JA01D)
CAP, CERM, 75 pF, 100 V,+/- 5%, C0G/NP0, 0603; Manufacturer: MuRata; Polarized: N; CompType: Capacitor; Value: 75pF; U/M: EA; Cap_F: 0.000000000075; Tolerance_%: 5; VDC_V: 100; Value2: 100V; TaMin_C: -55; TaMax_C: 125; Cap_Case: 0603; SizeArea_mm2: 1.28; SizeAreaWB_mm2: 4.68; SizeX_mm: 1.6; SizeY_mm: 0.8; SizeZ_mm: 1; AEC Category: Q200
signal-integrity model Cap
simulation model Cap
footprint 0603
footprint 0603M
footprint 0603L
footprint 0603_HV
footprint 0603S
pins: 1, 2

## GRM1885C2A751JA01D
designator C?  ValueDisplayed: 750pF  (hidden comment: GRM1885C2A751JA01D)
CAP, CERM, 750 pF, 100 V,+/- 5%, C0G/NP0, 0603; Manufacturer: MuRata; Polarized: N; CompType: Capacitor; Value: 750pF; U/M: EA; Cap_F: 0.00000000075; Tolerance_%: 5; VDC_V: 100; Value2: 100V; TaMin_C: -55; TaMax_C: 125; Cap_Case: 0603; SizeArea_mm2: 1.28; SizeAreaWB_mm2: 4.68; SizeX_mm: 1.6; SizeY_mm: 0.8; SizeZ_mm: 1; AEC Category: Q200
signal-integrity model Cap
simulation model Cap
footprint 0603
footprint 0603M
footprint 0603L
footprint 0603_HV
footprint 0603S
pins: 1, 2

## GRM1885C2A820JA01D
designator C?  ValueDisplayed: 82pF  (hidden comment: GRM1885C2A820JA01D)
CAP, CERM, 82 pF, 100 V,+/- 5%, C0G/NP0, 0603; Manufacturer: MuRata; Polarized: N; CompType: Capacitor; Value: 82pF; U/M: EA; Cap_F: 0.000000000082; Tolerance_%: 5; VDC_V: 100; Value2: 100V; TaMin_C: -55; TaMax_C: 125; Cap_Case: 0603; SizeArea_mm2: 1.28; SizeAreaWB_mm2: 4.68; SizeX_mm: 1.6; SizeY_mm: 0.8; SizeZ_mm: 1; AEC Category: Q200
signal-integrity model Cap
simulation model Cap
footprint 0603
footprint 0603M
footprint 0603L
footprint 0603_HV
footprint 0603S
pins: 1, 2

## GRM1885C2A821JA01D
designator C?  ValueDisplayed: 820pF  (hidden comment: GRM1885C2A821JA01D)
CAP, CERM, 820 pF, 100 V,+/- 5%, C0G/NP0, 0603; Manufacturer: MuRata; Polarized: N; CompType: Capacitor; Value: 820pF; U/M: EA; Cap_F: 0.00000000082; Tolerance_%: 5; VDC_V: 100; Value2: 100V; TaMin_C: -55; TaMax_C: 125; Cap_Case: 0603; SizeArea_mm2: 1.28; SizeAreaWB_mm2: 4.68; SizeX_mm: 1.6; SizeY_mm: 0.8; SizeZ_mm: 1; AEC Category: Q200
signal-integrity model Cap
simulation model Cap
footprint 0603
footprint 0603M
footprint 0603L
footprint 0603_HV
footprint 0603S
pins: 1, 2

## GRM1885C2A910JA01D
designator C?  ValueDisplayed: 91pF  (hidden comment: GRM1885C2A910JA01D)
CAP, CERM, 91 pF, 100 V,+/- 5%, C0G/NP0, 0603; Manufacturer: MuRata; Polarized: N; CompType: Capacitor; Value: 91pF; U/M: EA; Cap_F: 0.000000000091; Tolerance_%: 5; VDC_V: 100; Value2: 100V; TaMin_C: -55; TaMax_C: 125; Cap_Case: 0603; SizeArea_mm2: 1.28; SizeAreaWB_mm2: 4.68; SizeX_mm: 1.6; SizeY_mm: 0.8; SizeZ_mm: 1; AEC Category: Q200
signal-integrity model Cap
simulation model Cap
footprint 0603
footprint 0603M
footprint 0603L
footprint 0603_HV
footprint 0603S
pins: 1, 2

## GRM1885C2A911JA01D
designator C?  ValueDisplayed: 910pF  (hidden comment: GRM1885C2A911JA01D)
CAP, CERM, 910 pF, 100 V,+/- 5%, C0G/NP0, 0603; Manufacturer: MuRata; Polarized: N; CompType: Capacitor; Value: 910pF; U/M: EA; Cap_F: 0.00000000091; Tolerance_%: 5; VDC_V: 100; Value2: 100V; TaMin_C: -55; TaMax_C: 125; Cap_Case: 0603; SizeArea_mm2: 1.28; SizeAreaWB_mm2: 4.68; SizeX_mm: 1.6; SizeY_mm: 0.8; SizeZ_mm: 1; AEC Category: Q200
signal-integrity model Cap
simulation model Cap
footprint 0603
footprint 0603M
footprint 0603L
footprint 0603_HV
footprint 0603S
pins: 1, 2

## GRM2165C1H101JA01D
designator C?  ValueDisplayed: 100pF  (hidden comment: GRM2165C1H101JA01D)
CAP, CERM, 100 pF, 50 V,+/- 5%, C0G/NP0, 0805; Manufacturer: MuRata; Polarized: N; CompType: Capacitor; Value: 100pF; U/M: EA; Cap_F: 0.0000000001; Tolerance_%: 5; VDC_V: 50; Value2: 50V; TaMin_C: -55; TaMax_C: 125; Cap_Case: 0805; SizeArea_mm2: 2.5; SizeAreaWB_mm2: 6.75; SizeX_mm: 2; SizeY_mm: 1.25; SizeZ_mm: 1.45; AEC Category: Q200; Green_Lifecycle: Active; Green_REACh: Passed
signal-integrity model Cap
simulation model Cap
footprint 0805_HV
footprint 0805_HV1
footprint 0805
footprint 0805M
footprint 0805L
pins: 1, 2

## GRM2165C1H102JA01D
designator C?  ValueDisplayed: 1000pF  (hidden comment: GRM2165C1H102JA01D)
CAP, CERM, 1000 pF, 50 V,+/- 5%, C0G/NP0, 0805; Manufacturer: MuRata; Polarized: N; CompType: Capacitor; Value: 1000pF; U/M: EA; Cap_F: 0.000000001; Tolerance_%: 5; VDC_V: 50; Value2: 50V; TaMin_C: -55; TaMax_C: 125; Cap_Case: 0805; SizeArea_mm2: 2.5; SizeAreaWB_mm2: 6.75; SizeX_mm: 2; SizeY_mm: 1.25; SizeZ_mm: 1.45; AEC Category: Q200; Green_Lifecycle: Active; Green_REACh: Passed
signal-integrity model Cap
simulation model Cap
footprint 0805_HV
footprint 0805_HV1
footprint 0805
footprint 0805M
footprint 0805L
pins: 1, 2

## GRM2165C1H112JA01D
designator C?  ValueDisplayed: 1100pF  (hidden comment: GRM2165C1H112JA01D)
CAP, CERM, 1100 pF, 50 V,+/- 5%, C0G/NP0, 0805; Manufacturer: MuRata; Polarized: N; CompType: Capacitor; Value: 1100pF; U/M: EA; Cap_F: 0.0000000011; Tolerance_%: 5; VDC_V: 50; Value2: 50V; TaMin_C: -55; TaMax_C: 125; Cap_Case: 0805; SizeArea_mm2: 2.5; SizeAreaWB_mm2: 6.75; SizeX_mm: 2; SizeY_mm: 1.25; SizeZ_mm: 1.45; AEC Category: Q200
signal-integrity model Cap
simulation model Cap
footprint 0805_HV
footprint 0805_HV1
footprint 0805
footprint 0805M
footprint 0805L
pins: 1, 2

## GRM2165C1H121JA01D
designator C?  ValueDisplayed: 120pF  (hidden comment: GRM2165C1H121JA01D)
CAP, CERM, 120 pF, 50 V,+/- 5%, C0G/NP0, 0805; Manufacturer: MuRata; Polarized: N; CompType: Capacitor; Value: 120pF; U/M: EA; Cap_F: 0.00000000012; Tolerance_%: 5; VDC_V: 50; Value2: 50V; TaMin_C: -55; TaMax_C: 125; Cap_Case: 0805; SizeArea_mm2: 2.5; SizeAreaWB_mm2: 6.75; SizeX_mm: 2; SizeY_mm: 1.25; SizeZ_mm: 1.45; AEC Category: Q200; Green_Lifecycle: Active; Green_REACh: Passed
signal-integrity model Cap
simulation model Cap
footprint 0805_HV
footprint 0805_HV1
footprint 0805
footprint 0805M
footprint 0805L
pins: 1, 2

## GRM2165C1H122JA01D
designator C?  ValueDisplayed: 1200pF  (hidden comment: GRM2165C1H122JA01D)
CAP, CERM, 1200 pF, 50 V,+/- 5%, C0G/NP0, 0805; Manufacturer: MuRata; Polarized: N; CompType: Capacitor; Value: 1200pF; U/M: EA; Cap_F: 0.0000000012; Tolerance_%: 5; VDC_V: 50; Value2: 50V; TaMin_C: -55; TaMax_C: 125; Cap_Case: 0805; SizeArea_mm2: 2.5; SizeAreaWB_mm2: 6.75; SizeX_mm: 2; SizeY_mm: 1.25; SizeZ_mm: 1.45; AEC Category: Q200
signal-integrity model Cap
simulation model Cap
footprint 0805_HV
footprint 0805_HV1
footprint 0805
footprint 0805M
footprint 0805L
pins: 1, 2

## GRM2165C1H132JA01D
designator C?  ValueDisplayed: 1300pF  (hidden comment: GRM2165C1H132JA01D)
CAP, CERM, 1300 pF, 50 V,+/- 5%, C0G/NP0, 0805; Manufacturer: MuRata; Polarized: N; CompType: Capacitor; Value: 1300pF; U/M: EA; Cap_F: 0.0000000013; Tolerance_%: 5; VDC_V: 50; Value2: 50V; TaMin_C: -55; TaMax_C: 125; Cap_Case: 0805; SizeArea_mm2: 2.5; SizeAreaWB_mm2: 6.75; SizeX_mm: 2; SizeY_mm: 1.25; SizeZ_mm: 1.45; AEC Category: Q200
signal-integrity model Cap
simulation model Cap
footprint 0805_HV
footprint 0805_HV1
footprint 0805
footprint 0805M
footprint 0805L
pins: 1, 2

## GRM2165C1H151JA01D
designator C?  ValueDisplayed: 150pF  (hidden comment: GRM2165C1H151JA01D)
CAP, CERM, 150 pF, 50 V,+/- 5%, C0G/NP0, 0805; Manufacturer: MuRata; Polarized: N; CompType: Capacitor; Value: 150pF; U/M: EA; Cap_F: 0.00000000015; Tolerance_%: 5; VDC_V: 50; Value2: 50V; TaMin_C: -55; TaMax_C: 125; Cap_Case: 0805; SizeArea_mm2: 2.5; SizeAreaWB_mm2: 6.75; SizeX_mm: 2; SizeY_mm: 1.25; SizeZ_mm: 1.45; AEC Category: Q200
signal-integrity model Cap
simulation model Cap
footprint 0805_HV
footprint 0805_HV1
footprint 0805
footprint 0805M
footprint 0805L
pins: 1, 2

## GRM2165C1H152JA01D
designator C?  ValueDisplayed: 1500pF  (hidden comment: GRM2165C1H152JA01D)
CAP, CERM, 1500 pF, 50 V,+/- 5%, C0G/NP0, 0805; Manufacturer: MuRata; Polarized: N; CompType: Capacitor; Value: 1500pF; U/M: EA; Cap_F: 0.0000000015; Tolerance_%: 5; VDC_V: 50; Value2: 50V; TaMin_C: -55; TaMax_C: 125; Cap_Case: 0805; SizeArea_mm2: 2.5; SizeAreaWB_mm2: 6.75; SizeX_mm: 2; SizeY_mm: 1.25; SizeZ_mm: 1.45; AEC Category: Q200
signal-integrity model Cap
simulation model Cap
footprint 0805_HV
footprint 0805_HV1
footprint 0805
footprint 0805M
footprint 0805L
pins: 1, 2

## GRM2165C1H162JA01D
designator C?  ValueDisplayed: 1600pF  (hidden comment: GRM2165C1H162JA01D)
CAP, CERM, 1600 pF, 50 V,+/- 5%, C0G/NP0, 0805; Manufacturer: MuRata; Polarized: N; CompType: Capacitor; Value: 1600pF; U/M: EA; Cap_F: 0.0000000016; Tolerance_%: 5; VDC_V: 50; Value2: 50V; TaMin_C: -55; TaMax_C: 125; Cap_Case: 0805; SizeArea_mm2: 2.5; SizeAreaWB_mm2: 6.75; SizeX_mm: 2; SizeY_mm: 1.25; SizeZ_mm: 1.45; AEC Category: Q200
signal-integrity model Cap
simulation model Cap
footprint 0805_HV
footprint 0805_HV1
footprint 0805
footprint 0805M
footprint 0805L
pins: 1, 2

## GRM2165C1H181JA01D
designator C?  ValueDisplayed: 180pF  (hidden comment: GRM2165C1H181JA01D)
CAP, CERM, 180 pF, 50 V,+/- 5%, C0G/NP0, 0805; Manufacturer: MuRata; Polarized: N; CompType: Capacitor; Value: 180pF; U/M: EA; Cap_F: 0.00000000018; Tolerance_%: 5; VDC_V: 50; Value2: 50V; TaMin_C: -55; TaMax_C: 125; Cap_Case: 0805; SizeArea_mm2: 2.5; SizeAreaWB_mm2: 6.75; SizeX_mm: 2; SizeY_mm: 1.25; SizeZ_mm: 1.45; AEC Category: Q200
signal-integrity model Cap
simulation model Cap
footprint 0805_HV
footprint 0805_HV1
footprint 0805
footprint 0805M
footprint 0805L
pins: 1, 2

## GRM2165C1H182JA01D
designator C?  ValueDisplayed: 1800pF  (hidden comment: GRM2165C1H182JA01D)
CAP, CERM, 1800 pF, 50 V,+/- 5%, C0G/NP0, 0805; Manufacturer: MuRata; Polarized: N; CompType: Capacitor; Value: 1800pF; U/M: EA; Cap_F: 0.0000000018; Tolerance_%: 5; VDC_V: 50; Value2: 50V; TaMin_C: -55; TaMax_C: 125; Cap_Case: 0805; SizeArea_mm2: 2.5; SizeAreaWB_mm2: 6.75; SizeX_mm: 2; SizeY_mm: 1.25; SizeZ_mm: 1.45; AEC Category: Q200
signal-integrity model Cap
simulation model Cap
footprint 0805_HV
footprint 0805_HV1
footprint 0805
footprint 0805M
footprint 0805L
pins: 1, 2

## GRM2165C1H202JA01D
designator C?  ValueDisplayed: 2000pF  (hidden comment: GRM2165C1H202JA01D)
CAP, CERM, 2000 pF, 50 V,+/- 5%, C0G/NP0, 0805; Manufacturer: MuRata; Polarized: N; CompType: Capacitor; Value: 2000pF; U/M: EA; Cap_F: 0.000000002; Tolerance_%: 5; VDC_V: 50; Value2: 50V; TaMin_C: -55; TaMax_C: 125; Cap_Case: 0805; SizeArea_mm2: 2.5; SizeAreaWB_mm2: 6.75; SizeX_mm: 2; SizeY_mm: 1.25; SizeZ_mm: 1.45; AEC Category: Q200
signal-integrity model Cap
simulation model Cap
footprint 0805_HV
footprint 0805_HV1
footprint 0805
footprint 0805M
footprint 0805L
pins: 1, 2

## GRM2165C1H221JA01D
designator C?  ValueDisplayed: 220pF  (hidden comment: GRM2165C1H221JA01D)
CAP, CERM, 220 pF, 50 V,+/- 5%, C0G/NP0, 0805; Manufacturer: MuRata; Polarized: N; CompType: Capacitor; Value: 220pF; U/M: EA; Cap_F: 0.00000000022; Tolerance_%: 5; VDC_V: 50; Value2: 50V; TaMin_C: -55; TaMax_C: 125; Cap_Case: 0805; SizeArea_mm2: 2.5; SizeAreaWB_mm2: 6.75; SizeX_mm: 2; SizeY_mm: 1.25; SizeZ_mm: 1.45; AEC Category: Q200
signal-integrity model Cap
simulation model Cap
footprint 0805_HV
footprint 0805_HV1
footprint 0805
footprint 0805M
footprint 0805L
pins: 1, 2

## GRM2165C1H222FA01D
designator C?  ValueDisplayed: 2200pF  (hidden comment: GRM2165C1H222FA01D)
CAP, CERM, 2200 pF, 50 V,+/- 1%, C0G/NP0, 0805; Manufacturer: MuRata; Polarized: N; CompType: Capacitor; Value: 2200pF; U/M: EA; Cap_F: 0.0000000022; Tolerance_%: 1; VDC_V: 50; Value2: 50V; TaMin_C: -55; TaMax_C: 125; Cap_Case: 0805; SizeArea_mm2: 2.5; SizeAreaWB_mm2: 6.75; SizeX_mm: 2; SizeY_mm: 1.25; SizeZ_mm: 1.45; AEC Category: Q200
signal-integrity model Cap
simulation model Cap
footprint 0805_HV
footprint 0805_HV1
footprint 0805
footprint 0805M
footprint 0805L
pins: 1, 2

## GRM2165C1H222JA01D
designator C?  ValueDisplayed: 2200pF  (hidden comment: GRM2165C1H222JA01D)
CAP, CERM, 2200 pF, 50 V,+/- 5%, C0G/NP0, 0805; Manufacturer: MuRata; Polarized: N; CompType: Capacitor; Value: 2200pF; U/M: EA; Cap_F: 0.0000000022; Tolerance_%: 5; VDC_V: 50; Value2: 50V; TaMin_C: -55; TaMax_C: 125; Cap_Case: 0805; SizeArea_mm2: 2.5; SizeAreaWB_mm2: 6.75; SizeX_mm: 2; SizeY_mm: 1.25; SizeZ_mm: 1.45; AEC Category: Q200; Green_Lifecycle: Active; Green_REACh: Passed
signal-integrity model Cap
simulation model Cap
footprint 0805_HV
footprint 0805_HV1
footprint 0805
footprint 0805M
footprint 0805L
pins: 1, 2

## GRM2165C1H242JA01D
designator C?  ValueDisplayed: 2400pF  (hidden comment: GRM2165C1H242JA01D)
CAP, CERM, 2400 pF, 50 V,+/- 5%, C0G/NP0, 0805; Manufacturer: MuRata; Polarized: N; CompType: Capacitor; Value: 2400pF; U/M: EA; Cap_F: 0.0000000024; Tolerance_%: 5; VDC_V: 50; Value2: 50V; TaMin_C: -55; TaMax_C: 125; Cap_Case: 0805; SizeArea_mm2: 2.5; SizeAreaWB_mm2: 6.75; SizeX_mm: 2; SizeY_mm: 1.25; SizeZ_mm: 1.45; AEC Category: Q200
signal-integrity model Cap
simulation model Cap
footprint 0805_HV
footprint 0805_HV1
footprint 0805
footprint 0805M
footprint 0805L
pins: 1, 2

## GRM2165C1H271JA01D
designator C?  ValueDisplayed: 270pF  (hidden comment: GRM2165C1H271JA01D)
CAP, CERM, 270 pF, 50 V,+/- 5%, C0G/NP0, 0805; Manufacturer: MuRata; Polarized: N; CompType: Capacitor; Value: 270pF; U/M: EA; Cap_F: 0.00000000027; Tolerance_%: 5; VDC_V: 50; Value2: 50V; TaMin_C: -55; TaMax_C: 125; Cap_Case: 0805; SizeArea_mm2: 2.5; SizeAreaWB_mm2: 6.75; SizeX_mm: 2; SizeY_mm: 1.25; SizeZ_mm: 1.45; AEC Category: Q200
signal-integrity model Cap
simulation model Cap
footprint 0805_HV
footprint 0805_HV1
footprint 0805
footprint 0805M
footprint 0805L
pins: 1, 2

## GRM2165C1H272JA01D
designator C?  ValueDisplayed: 2700pF  (hidden comment: GRM2165C1H272JA01D)
CAP, CERM, 2700 pF, 50 V,+/- 5%, C0G/NP0, 0805; Manufacturer: MuRata; Polarized: N; CompType: Capacitor; Value: 2700pF; U/M: EA; Cap_F: 0.0000000027; Tolerance_%: 5; VDC_V: 50; Value2: 50V; TaMin_C: -55; TaMax_C: 125; Cap_Case: 0805; SizeArea_mm2: 2.5; SizeAreaWB_mm2: 6.75; SizeX_mm: 2; SizeY_mm: 1.25; SizeZ_mm: 1.45; AEC Category: Q200
signal-integrity model Cap
simulation model Cap
footprint 0805_HV
footprint 0805_HV1
footprint 0805
footprint 0805M
footprint 0805L
pins: 1, 2

## GRM2165C1H302JA01D
designator C?  ValueDisplayed: 3000pF  (hidden comment: GRM2165C1H302JA01D)
CAP, CERM, 3000 pF, 50 V,+/- 5%, C0G/NP0, 0805; Manufacturer: MuRata; Polarized: N; CompType: Capacitor; Value: 3000pF; U/M: EA; Cap_F: 0.000000003; Tolerance_%: 5; VDC_V: 50; Value2: 50V; TaMin_C: -55; TaMax_C: 125; Cap_Case: 0805; SizeArea_mm2: 2.5; SizeAreaWB_mm2: 6.75; SizeX_mm: 2; SizeY_mm: 1.25; SizeZ_mm: 1.45; AEC Category: Q200
signal-integrity model Cap
simulation model Cap
footprint 0805_HV
footprint 0805_HV1
footprint 0805
footprint 0805M
footprint 0805L
pins: 1, 2

## GRM2165C1H331JA01D
designator C?  ValueDisplayed: 330pF  (hidden comment: GRM2165C1H331JA01D)
CAP, CERM, 330 pF, 50 V,+/- 5%, C0G/NP0, 0805; Manufacturer: MuRata; Polarized: N; CompType: Capacitor; Value: 330pF; U/M: EA; Cap_F: 0.00000000033; Tolerance_%: 5; VDC_V: 50; Value2: 50V; TaMin_C: -55; TaMax_C: 125; Cap_Case: 0805; SizeArea_mm2: 2.5; SizeAreaWB_mm2: 6.75; SizeX_mm: 2; SizeY_mm: 1.25; SizeZ_mm: 1.45; AEC Category: Q200
signal-integrity model Cap
simulation model Cap
footprint 0805_HV
footprint 0805_HV1
footprint 0805
footprint 0805M
footprint 0805L
pins: 1, 2

## GRM2165C1H332JA01D
designator C?  ValueDisplayed: 3300pF  (hidden comment: GRM2165C1H332JA01D)
CAP, CERM, 3300 pF, 50 V,+/- 5%, C0G/NP0, 0805; Manufacturer: MuRata; Polarized: N; CompType: Capacitor; Value: 3300pF; U/M: EA; Cap_F: 0.0000000033; Tolerance_%: 5; VDC_V: 50; Value2: 50V; TaMin_C: -55; TaMax_C: 125; Cap_Case: 0805; SizeArea_mm2: 2.5; SizeAreaWB_mm2: 6.75; SizeX_mm: 2; SizeY_mm: 1.25; SizeZ_mm: 1.45; AEC Category: Q200
signal-integrity model Cap
simulation model Cap
footprint 0805_HV
footprint 0805_HV1
footprint 0805
footprint 0805M
footprint 0805L
pins: 1, 2

## GRM2165C1H362JA01D
designator C?  ValueDisplayed: 3600pF  (hidden comment: GRM2165C1H362JA01D)
CAP, CERM, 3600 pF, 50 V,+/- 5%, C0G/NP0, 0805; Manufacturer: MuRata; Polarized: N; CompType: Capacitor; Value: 3600pF; U/M: EA; Cap_F: 0.0000000036; Tolerance_%: 5; VDC_V: 50; Value2: 50V; TaMin_C: -55; TaMax_C: 125; Cap_Case: 0805; SizeArea_mm2: 2.5; SizeAreaWB_mm2: 6.75; SizeX_mm: 2; SizeY_mm: 1.25; SizeZ_mm: 1.45; AEC Category: Q200
signal-integrity model Cap
simulation model Cap
footprint 0805_HV
footprint 0805_HV1
footprint 0805
footprint 0805M
footprint 0805L
pins: 1, 2

## GRM2165C1H391JA01D
designator C?  ValueDisplayed: 390pF  (hidden comment: GRM2165C1H391JA01D)
CAP, CERM, 390 pF, 50 V,+/- 5%, C0G/NP0, 0805; Manufacturer: MuRata; Polarized: N; CompType: Capacitor; Value: 390pF; U/M: EA; Cap_F: 0.00000000039; Tolerance_%: 5; VDC_V: 50; Value2: 50V; TaMin_C: -55; TaMax_C: 125; Cap_Case: 0805; SizeArea_mm2: 2.5; SizeAreaWB_mm2: 6.75; SizeX_mm: 2; SizeY_mm: 1.25; SizeZ_mm: 1.45; AEC Category: Q200
signal-integrity model Cap
simulation model Cap
footprint 0805_HV
footprint 0805_HV1
footprint 0805
footprint 0805M
footprint 0805L
pins: 1, 2

## GRM2165C1H392JA01D
designator C?  ValueDisplayed: 3900pF  (hidden comment: GRM2165C1H392JA01D)
CAP, CERM, 3900 pF, 50 V,+/- 5%, C0G/NP0, 0805; Manufacturer: MuRata; Polarized: N; CompType: Capacitor; Value: 3900pF; U/M: EA; Cap_F: 0.0000000039; Tolerance_%: 5; VDC_V: 50; Value2: 50V; TaMin_C: -55; TaMax_C: 125; Cap_Case: 0805; SizeArea_mm2: 2.5; SizeAreaWB_mm2: 6.75; SizeX_mm: 2; SizeY_mm: 1.25; SizeZ_mm: 1.45; AEC Category: Q200
signal-integrity model Cap
simulation model Cap
footprint 0805_HV
footprint 0805_HV1
footprint 0805
footprint 0805M
footprint 0805L
pins: 1, 2

## GRM2165C1H432JA01D
designator C?  ValueDisplayed: 4300pF  (hidden comment: GRM2165C1H432JA01D)
CAP, CERM, 4300 pF, 50 V,+/- 5%, C0G/NP0, 0805; Manufacturer: MuRata; Polarized: N; CompType: Capacitor; Value: 4300pF; U/M: EA; Cap_F: 0.0000000043; Tolerance_%: 5; VDC_V: 50; Value2: 50V; TaMin_C: -55; TaMax_C: 125; Cap_Case: 0805; SizeArea_mm2: 2.5; SizeAreaWB_mm2: 6.75; SizeX_mm: 2; SizeY_mm: 1.25; SizeZ_mm: 1.45; AEC Category: Q200
signal-integrity model Cap
simulation model Cap
footprint 0805_HV
footprint 0805_HV1
footprint 0805
footprint 0805M
footprint 0805L
pins: 1, 2

## GRM2165C1H471JA01D
designator C?  ValueDisplayed: 470pF  (hidden comment: GRM2165C1H471JA01D)
CAP, CERM, 470 pF, 50 V,+/- 5%, C0G/NP0, 0805; Manufacturer: MuRata; Polarized: N; CompType: Capacitor; Value: 470pF; U/M: EA; Cap_F: 0.00000000047; Tolerance_%: 5; VDC_V: 50; Value2: 50V; TaMin_C: -55; TaMax_C: 125; Cap_Case: 0805; SizeArea_mm2: 2.5; SizeAreaWB_mm2: 6.75; SizeX_mm: 2; SizeY_mm: 1.25; SizeZ_mm: 1.45; AEC Category: Q200; Green_Lifecycle: Active; Green_REACh: Passed
signal-integrity model Cap
simulation model Cap
footprint 0805_HV
footprint 0805_HV1
footprint 0805
footprint 0805M
footprint 0805L
pins: 1, 2

## GRM2165C1H472FA01D
designator C?  ValueDisplayed: 4700pF  (hidden comment: GRM2165C1H472FA01D)
CAP, CERM, 4700 pF, 50 V,+/- 1%, C0G/NP0, 0805; Manufacturer: MuRata; Polarized: N; CompType: Capacitor; Value: 4700pF; U/M: EA; Cap_F: 0.0000000047; Tolerance_%: 1; VDC_V: 50; Value2: 50V; TaMin_C: -55; TaMax_C: 125; Cap_Case: 0805; SizeArea_mm2: 2.5; SizeAreaWB_mm2: 6.75; SizeX_mm: 2; SizeY_mm: 1.25; SizeZ_mm: 1.45; AEC Category: Q200
signal-integrity model Cap
simulation model Cap
footprint 0805_HV
footprint 0805_HV1
footprint 0805
footprint 0805M
footprint 0805L
pins: 1, 2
